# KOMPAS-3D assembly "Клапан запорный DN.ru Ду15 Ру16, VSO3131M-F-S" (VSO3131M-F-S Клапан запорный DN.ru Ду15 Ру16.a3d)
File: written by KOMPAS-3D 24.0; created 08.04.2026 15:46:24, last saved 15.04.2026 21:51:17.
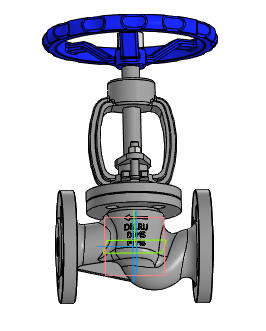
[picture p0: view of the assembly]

Document properties: Автор: R2D2; Полное имя файла: E:\Работа\Зайцев\VSO3131M-F-S Клапан запорный DN.ru Ду15-100 Ру16\DN15\исходные материалы\VSO3131M-F-S Клапан запорный DN.ru Ду15 Ру16.a3d

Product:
- Component [detail]: Клапан запорный DN.ru Ду15 Ру16  | designation VSO1121M-F-S  | qty 1  | pos. 1  | Масса: 3.1; Раздел спецификации: Прочие изделия; Примечание: D090-01942; Автор: R2D2; source file: 1.m3d
- Component [detail]: Клапан запорный DN.ru Ду15 Ру16  | designation VSO1121M-F-S  | qty 1  | Масса: 3.1; Раздел спецификации: Прочие изделия; Примечание: D090-01942; Автор: R2D2; source file: 2.m3d
- Component [standard]: Фланец 15-1-01-1-B-ВЧ40-I-dв 19 ГОСТ 33259-2015  | qty 2  | Материал: ВЧ40 ГОСТ 7293-85 (density 7200 kg/m3); Масса: 0.29; Раздел спецификации: Стандартные изделия; additional columns: BOSimple***Material:38d6725a-5efe-48e1-b177-a7817acb862a
- Part/product: Клапан запорный DN.ru Ду15 Ру16  | designation VSO3131M-F-S
    Масса: 3.45
    Раздел спецификации: Прочие изделия
    Примечание: D090-02946

Expressions: D090-01942
Referenced files in E:\Работа\Зайцев\VSO3131M-F-S Клапан запорный DN.ru Ду15-100 Ру40\DN15\исходные материалы\: 1.m3d, 2.m3d
Referenced files in E:\Работа\Зайцев\VSO3131M-F-S Клапан запорный DN.ru Ду15-100 Ру16\DN15\исходные материалы\: 1.m3d, 2.m3d
Referenced files in C:\Program Files\ASCON\KOMPAS-3D v24\Libs\PolynomLib\DATA\vault\Methods\Kompas\3D\: PLib_Flange_GOST_33259_1401.m3d
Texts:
  VSO1121M-F-S
  Фланцы ГОСТ Р 54432
  ВЧ40
  BOSimple***PART:3f5f0d7e-d4da-47dc-6145-6a7f26b7079a***SHORTLOC:B6A6_23E38AE8DB154823[I;1;Круглый;15;1;19;0;ВЧ40 ГОСТ 7293-85]
  BOSimple***Material:38d6725a-5efe-48e1-b177-a7817acb862a
  Программные изделия  и базы данных
  VSO3131M-F-S
  VSO1121M-F-S Клапан запорный DN.ru Ду15 Ру16
  Фланец 15-1-01-1-B-ВЧ40-I-dв 19 ГОСТ 33259-2015 (1)
  Ch34
  Фланец 15-1-01-1-B-ВЧ40-I-dв 19 ГОСТ 33259-2015 (2)
  Ось Z.Начало координат
  Ось Y.Начало координат
  Плоскость ZY.Начало координат
  Плоскость ZX.Начало координат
